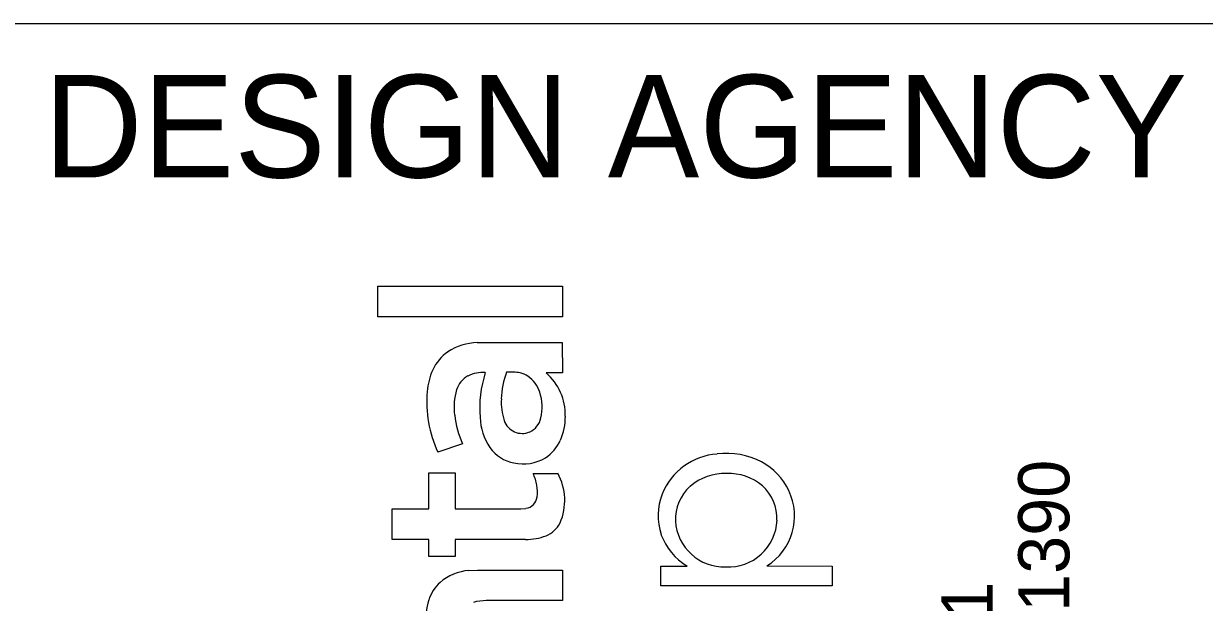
# Model space of a CAD drawing. Extents: x 0 to 34, y 0 to 22.
# Drawn here: x 32.03 to 33.181, y 3.936 to 4.5 of the extents above; entities that cross this region are included whole.
import ezdxf

# ---------------------------------------------------------------- set-up
doc = ezdxf.new("R2010")
doc.units = 0
for name, color, linetype in [('SH_Border', 7, 'Continuous'), ('SH_Data', 7, 'Continuous'), ('SH_Text', 7, 'Continuous')]:
    doc.layers.add(name, color=color, linetype=linetype)

msp = doc.modelspace()

# ---------------------------------------------------------------- linework, layer by layer
at = {"layer": 'SH_Border'}
msp.add_line((32, 4.5), (33.5, 4.5), dxfattribs=at)
at = {"layer": 'SH_Text'}
for p, q in [((32.3756, 4.2141), (32.3756, 4.244)), ((32.3756, 4.244), (32.5557, 4.244)), ((32.5557, 4.244), (32.5557, 4.2141)), ((32.5557, 4.2141), (32.3756, 4.2141)), ((32.4727, 4.189), (32.5555, 4.1892)), ((32.5555, 4.1892), (32.5557, 4.1596)), ((32.5557, 4.1596), (32.5397, 4.1596)), ((32.4582, 4.0904), (32.4343, 4.0823)), ((32.4254, 4.027), (32.4255, 4.0621)), ((32.4255, 4.0621), (32.4511, 4.0621)), ((32.4511, 4.0621), (32.4512, 4.027)), ((32.527, 4.0616), (32.5511, 4.0616)), ((32.3896, 3.9972), (32.3896, 4.027)), ((32.3896, 4.027), (32.4254, 4.027)), ((32.4512, 4.027), (32.515, 4.027)), ((32.515, 4.027), (32.52, 4.0275)), ((32.4254, 3.9972), (32.3896, 3.9972)), ((32.4254, 3.9807), (32.4254, 3.9972)), ((32.5197, 3.9972), (32.4511, 3.9972)), ((32.4511, 3.9972), (32.4511, 3.9807)), ((32.4511, 3.9807), (32.4254, 3.9807)), ((32.6515, 3.9521), (32.6515, 3.9711)), ((32.6515, 3.9711), (32.6771, 3.9711)), ((32.7549, 3.9713), (32.8186, 3.9711)), ((32.8186, 3.9711), (32.8184, 3.9521)), ((32.4644, 3.9669), (32.4729, 3.9673)), ((32.4729, 3.9673), (32.5557, 3.9673)), ((32.5557, 3.9673), (32.5557, 3.9375)), ((32.8184, 3.9521), (32.6515, 3.9521)), ((32.5557, 3.9375), (32.4814, 3.9375))]:
    msp.add_line(p, q, dxfattribs=at)
msp.add_lwpolyline([(32.3756, 4.2141), (32.3756, 4.244), (32.5557, 4.244), (32.5557, 4.2141)], close=True, dxfattribs=at)
for points in [[(32.4727, 4.189), (32.5555, 4.1892), (32.5557, 4.1596)], [(32.5557, 4.1596), (32.5397, 4.1596)], [(32.4582, 4.0904), (32.4343, 4.0823)], [(32.5197, 3.9972), (32.4511, 3.9972), (32.4511, 3.9807), (32.4254, 3.9807), (32.4254, 3.9972), (32.3896, 3.9972), (32.3896, 4.027), (32.4254, 4.027), (32.4255, 4.0621), (32.4511, 4.0621), (32.4512, 4.027), (32.515, 4.027), (32.52, 4.0275)], [(32.527, 4.0616), (32.5511, 4.0616)], [(32.7549, 3.9713), (32.8186, 3.9711), (32.8184, 3.9521), (32.6515, 3.9521)], [(32.6515, 3.9521), (32.6515, 3.9711), (32.6771, 3.9711)], [(32.4644, 3.9669), (32.4729, 3.9673), (32.5557, 3.9673), (32.5557, 3.9375), (32.4814, 3.9375)]]:
    msp.add_lwpolyline(points, dxfattribs=at)
for centre, radius, start, end in [((32.4685, 4.1447), 0.043, 124.537, 155.6594), ((32.4685, 4.1447), 0.043, 124.537, 155.6594), ((32.4745, 4.1326), 0.0565, 91.8942, 122.6317), ((32.4745, 4.1326), 0.0565, 91.8942, 122.6317), ((32.4882, 4.1361), 0.0646, 155.9764, 175.3149), ((32.4882, 4.1361), 0.0646, 155.9764, 175.3149), ((32.4753, 4.1356), 0.024, 119.4252, 161.6629), ((32.4753, 4.1356), 0.024, 119.4252, 161.6629), ((32.4779, 4.1278), 0.0321, 85.3802, 116.6222), ((32.4779, 4.1278), 0.0321, 85.3802, 116.6222), ((32.5879, 4.1251), 0.1129, 162.0821, 184.5285), ((32.5879, 4.1251), 0.1129, 162.0821, 184.5285), ((32.5801, 4.1313), 0.0841, 159.8366, 178.0362), ((32.5801, 4.1313), 0.0841, 159.8366, 178.0362), ((32.5051, 4.1074), 0.053, 79.6696, 94.2322), ((32.5051, 4.1074), 0.053, 79.6696, 94.2322), ((32.5089, 4.1364), 0.0238, 56.8913, 76.2149), ((32.5089, 4.1364), 0.0238, 56.8913, 76.2149), ((32.5052, 4.1318), 0.0297, 17.5984, 55.7282), ((32.5052, 4.1318), 0.0297, 17.5984, 55.7282), ((32.5055, 4.1191), 0.0529, 358.0746, 49.762), ((32.5055, 4.1191), 0.0529, 358.0746, 49.762), ((32.5076, 4.1265), 0.0576, 163.1369, 188.1675), ((32.5076, 4.1265), 0.0576, 163.1369, 188.1675), ((32.5364, 4.1308), 0.113, 174.6101, 205.3899), ((32.5364, 4.1308), 0.113, 174.6101, 205.3899), ((32.5466, 4.1303), 0.0506, 175.5903, 199.8857), ((32.5466, 4.1303), 0.0506, 175.5903, 199.8857), ((32.4916, 4.1264), 0.0443, 345.9408, 18.9919), ((32.4916, 4.1264), 0.0443, 345.9408, 18.9919), ((32.5473, 4.1297), 0.0973, 186.7598, 203.7981), ((32.5473, 4.1297), 0.0973, 186.7598, 203.7981), ((32.5328, 4.1187), 0.0575, 182.5676, 213.7144), ((32.5328, 4.1187), 0.0575, 182.5676, 213.7144), ((32.5164, 4.1189), 0.0184, 198.2844, 293.3081), ((32.5164, 4.1189), 0.0184, 198.2844, 293.3081), ((32.5152, 4.1199), 0.0199, 295.2883, 347.4639), ((32.5152, 4.1199), 0.0199, 295.2883, 347.4639), ((32.5019, 4.1168), 0.0566, 336.016, 0.5951), ((32.5019, 4.1168), 0.0566, 336.016, 0.5951), ((32.5149, 4.1078), 0.0366, 215.0668, 259.8133), ((32.5149, 4.1078), 0.0366, 215.0668, 259.8133), ((32.5175, 4.1097), 0.0394, 303.4436, 336.18), ((32.5175, 4.1097), 0.0394, 303.4436, 336.18), ((32.5175, 4.1131), 0.0423, 257.5256, 300.882), ((32.5175, 4.1131), 0.0423, 257.5256, 300.882), ((32.7108, 4.0182), 0.0624, 93.9866, 158.3119), ((32.7108, 4.0182), 0.0624, 93.9866, 158.3119), ((32.7156, 4.0065), 0.0746, 62.6889, 97.0135), ((32.7156, 4.0065), 0.0746, 62.6889, 97.0135), ((32.7212, 4.0191), 0.0608, 25.0657, 61.9602), ((32.7212, 4.0191), 0.0608, 25.0657, 61.9602), ((32.4863, 4.042), 0.0452, 10.1545, 25.723), ((32.4863, 4.042), 0.0452, 10.1545, 25.723), ((32.503, 4.0351), 0.0549, 336.589, 28.8991), ((32.503, 4.0351), 0.0549, 336.589, 28.8991), ((32.7138, 4.0102), 0.0513, 87.8965, 131.1812), ((32.7138, 4.0102), 0.0513, 87.8965, 131.1812), ((32.7175, 4.0102), 0.0513, 49.9089, 92.0363), ((32.7175, 4.0102), 0.0513, 49.9089, 92.0363), ((32.4957, 4.0436), 0.0356, 351.914, 10.2059), ((32.4957, 4.0436), 0.0356, 351.914, 10.2059), ((32.707, 4.0202), 0.0581, 158.656, 198.171), ((32.707, 4.0202), 0.0581, 158.656, 198.171), ((32.7092, 4.0167), 0.0434, 132.3289, 182.0949), ((32.7092, 4.0167), 0.0434, 132.3289, 182.0949), ((32.7215, 4.0173), 0.0433, 358.0487, 47.9447), ((32.7215, 4.0173), 0.0433, 358.0487, 47.9447), ((32.7245, 4.02), 0.0574, 301.9776, 25.6418), ((32.7245, 4.02), 0.0574, 301.9776, 25.6418), ((32.5184, 4.04), 0.0126, 277.6142, 353.7918), ((32.5184, 4.04), 0.0126, 277.6142, 353.7918), ((32.5291, 4.0261), 0.0275, 292.6889, 332.0598), ((32.5291, 4.0261), 0.0275, 292.6889, 332.0598), ((32.7135, 4.0181), 0.0478, 183.5974, 271.7045), ((32.7135, 4.0181), 0.0478, 183.5974, 271.7045), ((32.7172, 4.018), 0.0477, 267.3149, 357.4019), ((32.7172, 4.018), 0.0477, 267.3149, 357.4019), ((32.5209, 4.0486), 0.0514, 268.6727, 291.5235), ((32.5209, 4.0486), 0.0514, 268.6727, 291.5235), ((32.7103, 4.0243), 0.0627, 200.8399, 238.0162), ((32.7103, 4.0243), 0.0627, 200.8399, 238.0162), ((32.4687, 3.9172), 0.0499, 94.9706, 130.2248), ((32.4687, 3.9172), 0.0499, 94.9706, 130.2248), ((32.4635, 3.9255), 0.0402, 132.2238, 161.6823), ((32.4635, 3.9255), 0.0402, 132.2238, 161.6823), ((32.4787, 3.9211), 0.056, 162.274, 187.7917), ((32.4787, 3.9211), 0.056, 162.274, 187.7917), ((32.4811, 3.8915), 0.046, 89.6051, 105.3303), ((32.4811, 3.8915), 0.046, 89.6051, 105.3303)]:
    msp.add_arc(centre, radius, start, end, dxfattribs=at)

# ---------------------------------------------------------------- texts
at = {"layer": 'SH_Data'}
msp.add_text('DESIGN AGENCY', height=0.1, dxfattribs=at).set_placement((32.05, 4.35))
at = {"layer": 'SH_Text'}
for s, p in [('800.835.1390', (33.0497, 3.6671)), ('450 GRANT ST., AKRON, OH  44311', (32.9749, 2.8374))]:
    msp.add_text(s, height=0.049846, rotation=90, dxfattribs=at).set_placement(p)

doc.saveas('drawing.dxf')
